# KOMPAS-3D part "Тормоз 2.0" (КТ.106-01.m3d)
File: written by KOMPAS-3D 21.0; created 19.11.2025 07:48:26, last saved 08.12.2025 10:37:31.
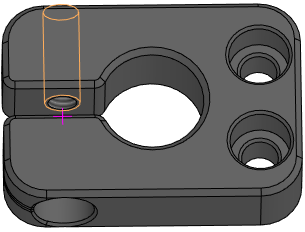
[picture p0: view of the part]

Document properties: Полное имя файла: C:\Users\User\Desktop\Pelorus PRO доработки\Тормоз\КТ.106-01.m3d; Автор: User

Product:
- Part/product: Тормоз 2.0
    Масса: 0.124883
    Форматы листов документа: A4

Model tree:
1. Эскиз:1
2. Элемент выдавливания:1
     Расстояние 1 = 13
3. Эскиз:2
4. Отверстие:2  (with: Элемент выдавливания:1)  (labels: M6)
     Глубина выреза = 19; Диаметр отверстия = 4.91747; Угол конуса дна = 118; Расстояние 1 = 6.5; Расстояние 2 = 10
5. M6  (with: Элемент выдавливания:1)  (labels: M6; cil0_24705-2004 coarse)
     Длина резьбы = 17; Шаг резьбы = 1; Номинальный диаметр резьбы = 6
6. Отверстие:3  (with: Элемент выдавливания:1)
     Глубина выреза = 40; Диаметр отверстия = 6.2; Угол конуса дна = 118; Расстояние 1 = 6.5; Расстояние 2 = 6.71915
7. Скругление:1  (with: Элемент выдавливания:1)
     Радиус = 7
8. Смещенная плоскость:1
     Расстояние = -10
9. Эскиз:3
10. Элемент выдавливания:2
     Расстояние 1 = 10; Расстояние 2 = -1.5
11. Элемент выдавливания:3  (with: Элемент выдавливания:1)
     Толщина стенки 1 = 2; Расстояние 2 = 6.5
12. Скругление:2  (with: Элемент выдавливания:1)
     Радиус = 2
13. Фаска:2  (with: Элемент выдавливания:3, Элемент выдавливания:2)
     Угол = 45; Длина 1 = 0.5; Длина 2 = 0.5
14. Фаска:4  (with: Элемент выдавливания:1)
     Угол = 45; Длина 1 = 1; Длина 2 = 1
